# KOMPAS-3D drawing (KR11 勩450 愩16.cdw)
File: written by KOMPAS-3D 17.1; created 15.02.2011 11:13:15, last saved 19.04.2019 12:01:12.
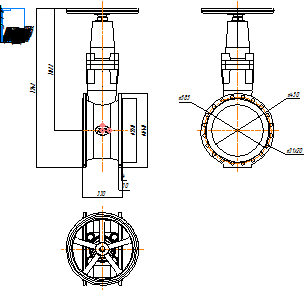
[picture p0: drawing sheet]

Title block, sheet 1: name: KR11 Ду450 Ру16; material: Внимание! Данный продукт является объектом авторского права ООО «Торговый Дом АДЛ». / Запрещается изменение, копирование, распространение / (в том числе путем копирования на другие сайты и ресурсы в Интернете) / или любое иное использование информации и объектов без предварительного / согласия правообладателя (ООО «Торговый Дом АДЛ»).; scale: 1:1; sheets: 1; organisation: ООО "Торговый дом АДЛ"; sheet format: A4; stored path: \\adlc.lan\data\АДЛ_ПКД\3D-модели\ADL production\Клиновые задвижки серии KR ГРАНАР\Клиновые задвижки KR11\KOMPAS 2D\KR11 Ду450 Ру16.cdw

Views: Спереди 1, Проекционный вид 2, Проекционный вид 3
Dimensions and other numbers on the sheet: 450; 585; 31; 330; 550; 640; 4; 30; 1022; 1342; 1:1; 1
